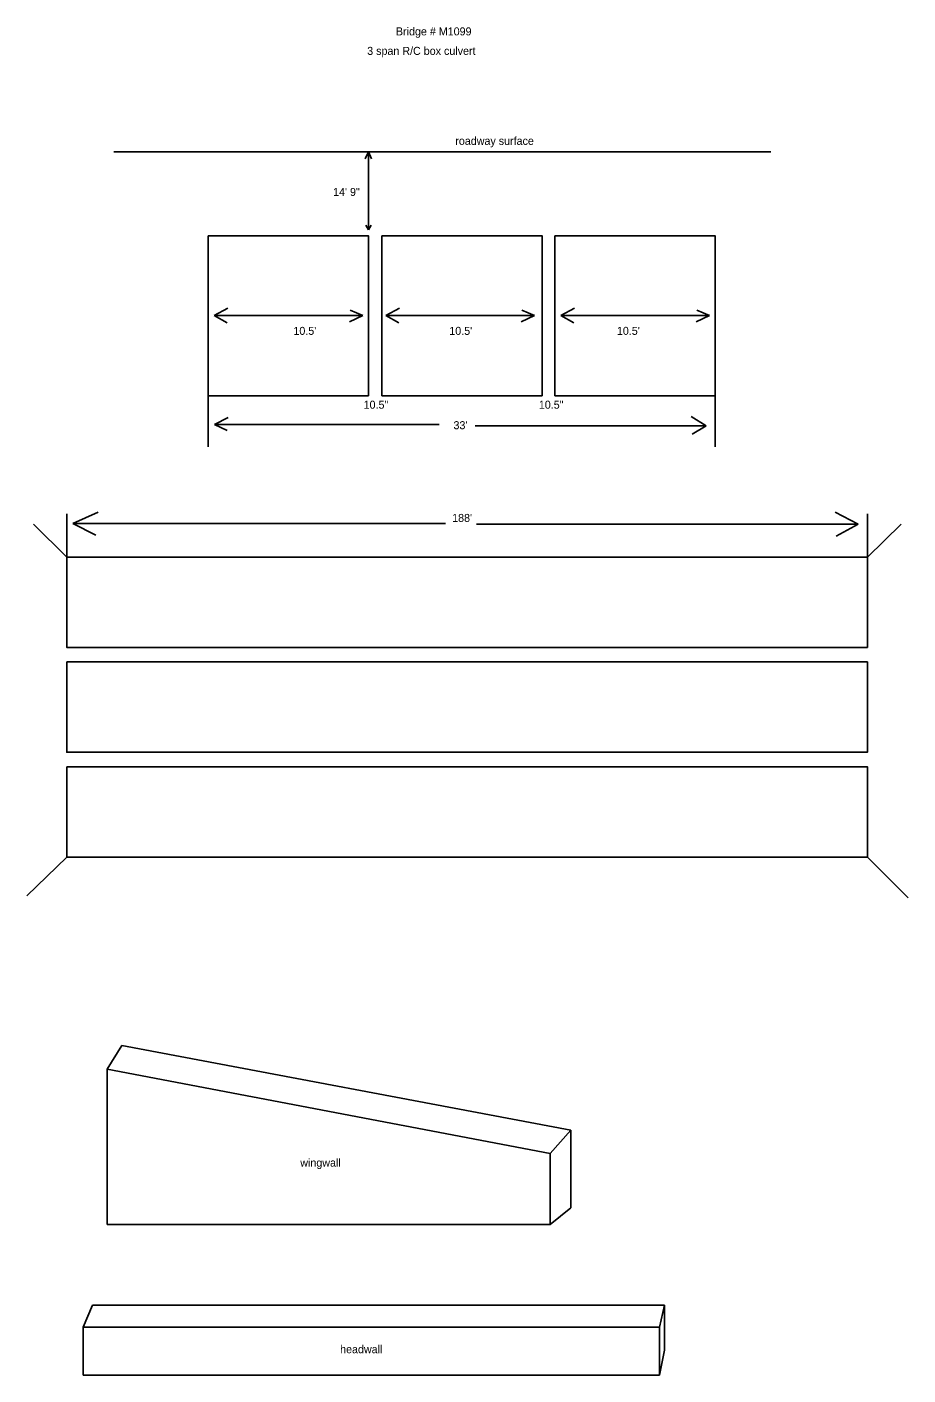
# Model space of a CAD drawing. Extents: x -629.7 to -574.7, y -353.6 to -269.4.
import ezdxf

# ---------------------------------------------------------------- set-up
doc = ezdxf.new("R2010")
doc.units = 0
doc.layers.add('Default', color=7, linetype='Continuous')

msp = doc.modelspace()

# ---------------------------------------------------------------- linework, layer by layer
at = {"layer": 'Default'}
for p, q in [((-608.404, -277.151), (-624.314, -277.151)), ((-608.404, -277.151), (-608.621, -277.594)), ((-608.404, -277.151), (-608.404, -281.469)), ((-608.404, -277.151), (-608.215, -277.605)), ((-608.404, -277.151), (-593.023, -277.151)), ((-593.023, -277.151), (-583.278, -277.151)), ((-608.404, -282.033), (-608.568, -281.752)), ((-608.404, -281.469), (-608.404, -282.033)), ((-608.404, -282.033), (-608.23, -281.752)), ((-618.035, -287.395), (-617.196, -286.924)), ((-608.765, -287.395), (-609.543, -287.047)), ((-607.312, -287.395), (-606.473, -286.924)), ((-598.042, -287.395), (-598.82, -287.047)), ((-596.39, -287.395), (-595.551, -286.924)), ((-587.12, -287.395), (-587.898, -287.047)), ((-618.035, -287.395), (-608.765, -287.395)), ((-618.035, -287.395), (-617.237, -287.845)), ((-608.765, -287.395), (-609.584, -287.784)), ((-607.312, -287.395), (-598.042, -287.395)), ((-607.312, -287.395), (-606.514, -287.845)), ((-598.042, -287.395), (-598.861, -287.784)), ((-596.39, -287.395), (-587.12, -287.395)), ((-596.39, -287.395), (-595.592, -287.845)), ((-587.12, -287.395), (-587.938, -287.784)), ((-618.404, -292.401), (-618.404, -295.589)), ((-586.759, -292.401), (-586.759, -295.589)), ((-618.014, -294.203), (-617.165, -293.767)), ((-587.319, -294.287), (-588.262, -293.706)), ((-618.014, -294.203), (-603.988, -294.203)), ((-618.014, -294.203), (-617.227, -294.576)), ((-601.749, -294.287), (-587.319, -294.287)), ((-587.319, -294.287), (-588.189, -294.794)), ((-627.248, -302.481), (-627.248, -299.775)), ((-626.864, -300.384), (-625.289, -299.667)), ((-577.839, -300.42), (-579.271, -299.667)), ((-577.248, -302.481), (-577.248, -299.775)), ((-627.248, -302.481), (-629.318, -300.418)), ((-603.587, -300.384), (-626.864, -300.384)), ((-626.864, -300.384), (-625.432, -301.1)), ((-601.653, -300.42), (-577.839, -300.42)), ((-577.839, -300.42), (-579.199, -301.172)), ((-577.248, -302.481), (-575.141, -300.418)), ((-627.248, -321.221), (-629.727, -323.642)), ((-577.248, -321.221), (-574.717, -323.769)), ((-624.713, -334.467), (-623.805, -332.984)), ((-623.805, -332.984), (-595.776, -338.273)), ((-624.713, -334.467), (-624.713, -344.186)), ((-624.713, -334.467), (-597.056, -339.743)), ((-597.056, -339.743), (-595.776, -338.273)), ((-595.776, -338.273), (-595.776, -343.139)), ((-597.056, -344.186), (-597.056, -339.743)), ((-597.056, -344.186), (-595.776, -343.139)), ((-624.713, -344.186), (-597.056, -344.186)), ((-626.212, -350.582), (-625.644, -349.207)), ((-625.644, -349.207), (-589.913, -349.207)), ((-590.23, -350.582), (-589.913, -349.207)), ((-589.913, -349.207), (-589.913, -349.207)), ((-589.913, -349.207), (-589.913, -352.038)), ((-626.212, -350.582), (-590.23, -350.582)), ((-626.212, -350.582), (-626.212, -353.582)), ((-590.23, -350.582), (-590.23, -353.582)), ((-589.913, -352.038), (-590.23, -353.582)), ((-626.212, -353.582), (-590.23, -353.582))]:
    msp.add_line(p, q, dxfattribs=at)
for points in [[(-618.404, -282.401), (-608.404, -282.401), (-608.404, -292.401), (-618.404, -292.401)], [(-607.564, -282.401), (-597.564, -282.401), (-597.564, -292.401), (-607.564, -292.401)], [(-596.759, -282.401), (-586.759, -282.401), (-586.759, -292.401), (-596.759, -292.401)], [(-627.248, -302.481), (-577.248, -302.481), (-577.248, -308.127), (-627.248, -308.127)], [(-627.248, -309.026), (-577.248, -309.026), (-577.248, -314.672), (-627.248, -314.672)], [(-627.248, -315.575), (-577.248, -315.575), (-577.248, -321.221), (-627.248, -321.221)]]:
    msp.add_lwpolyline(points, close=True, dxfattribs=at)

# ---------------------------------------------------------------- texts
for s, p in [('Bridge # M1099', (-606.69, -269.886)), ('3 span R/C box culvert', (-608.484, -271.104)), ('roadway surface', (-602.983, -276.727)), ('14\' 9"', (-610.614, -279.918)), ("10.5'", (-613.091, -288.595)), ("10.5'", (-603.358, -288.595)), ("10.5'", (-592.893, -288.595)), ('10.5"', (-608.708, -293.209)), ('10.5"', (-597.767, -293.209)), ('10.5"', (-597.767, -293.209)), ("33'", (-603.097, -294.49)), ("188'", (-603.18, -300.283)), ('wingwall', (-612.663, -340.563)), ('headwall', (-610.175, -352.218))]:
    msp.add_text(s, height=0.5, dxfattribs=at).set_placement(p)

doc.saveas('drawing.dxf')
